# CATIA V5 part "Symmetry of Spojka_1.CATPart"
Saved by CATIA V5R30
Part number: Symmetry of Spojka_1
Bounding box of the stored display mesh (mm): x -8.66 to 8.66, y -7.5 to 7.5, z -9 to 17
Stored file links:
  E:\Bakalarka\Model\Forma_v7\Symmetry of Spojka_1.CATPart
  E:\Bakalarka\Model\Forma_v7\Spojka_1.CATPart
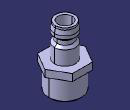
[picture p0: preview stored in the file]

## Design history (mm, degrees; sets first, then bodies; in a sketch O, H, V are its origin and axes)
Body1 (main body)
  Body2 "Body from original PartBody"
    Solid1: linked copy from another document
  Assemble1: tool Body2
